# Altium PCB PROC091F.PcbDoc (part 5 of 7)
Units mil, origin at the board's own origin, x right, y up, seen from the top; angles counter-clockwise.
Board outline 3590.95 x 906.17 mil, 8 copper layers (Top Layer, GND1, Sig1, PWR1, PWR2, Sig2, GND2, Bottom Layer), stack 63.146 mil thick; 420 components, 316 nets, 1432 pads, 774 vias.
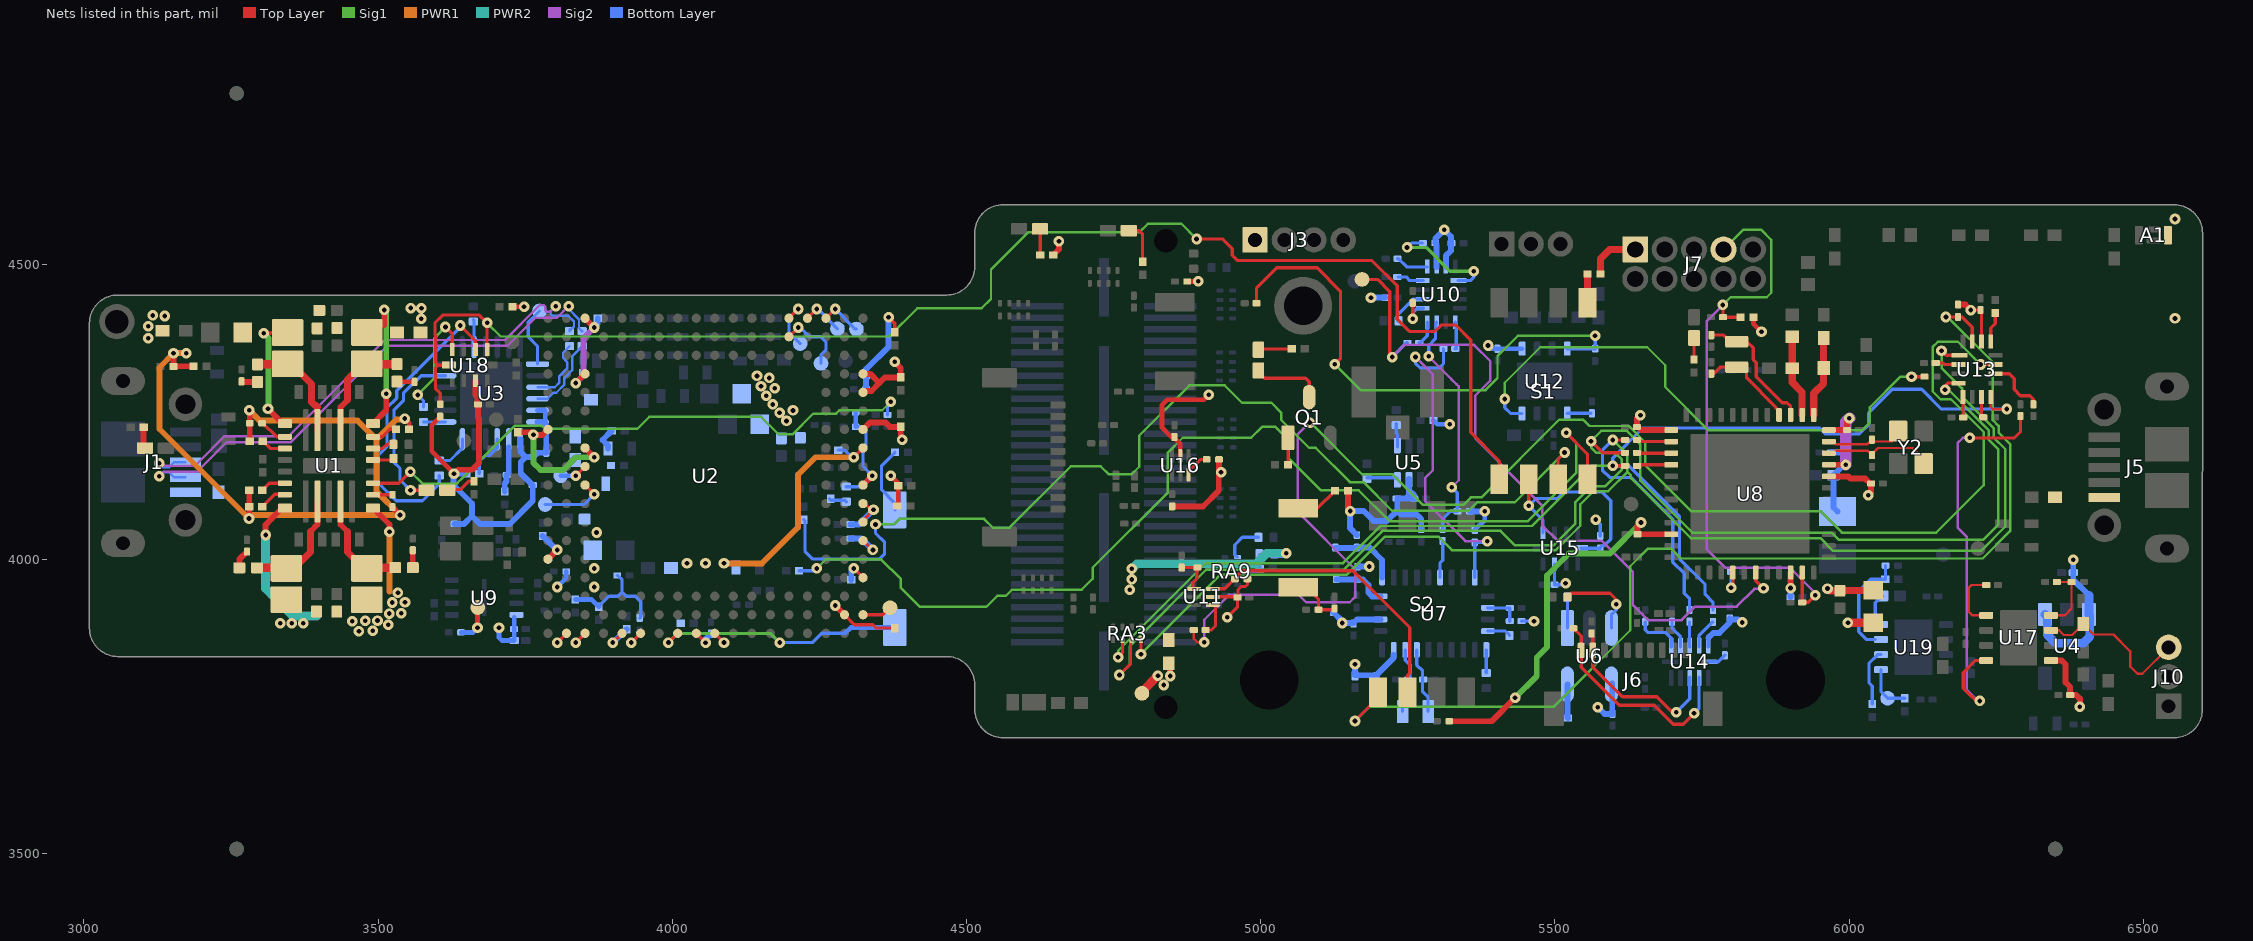
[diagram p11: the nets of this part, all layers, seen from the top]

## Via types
v1: diameter 18, hole 8, Top Layer to Bottom Layer, tented both sides, 737 vias
v2: diameter 19.68, hole 7.87, Top Layer to Bottom Layer, tented both sides, 36 vias
v3: diameter 17, hole 8, Top Layer to Bottom Layer, tented both sides, 1 vias

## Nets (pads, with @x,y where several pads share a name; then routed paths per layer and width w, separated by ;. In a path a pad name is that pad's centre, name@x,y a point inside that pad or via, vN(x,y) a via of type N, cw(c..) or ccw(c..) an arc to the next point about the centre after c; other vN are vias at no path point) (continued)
NetJ10_3: J10.3 R114.2 U17.7 | length 279.6
  Top Layer w4: U17.7@6343.09,3878.8 6356.9,3878.8 6364.64,3871.05 6379.2,3871.05 R114.2@6397.76,3889.61 6415.45,3871.92 6422.58,3871.92 6448.98,3871.92 6477.7,3843.2 6477.7,3817.28 6489.93,3805.05 6498.05,3805.05 J10.3@6543,3850
NetLD1_1: LD1.1 R39.2 | length 36.4
  Top Layer w10: R39.2@3101.69,4224 3101.69,4190.75 LD1.1@3103.94,4188.5
NetLD2_1: LD2.1 R13.2 | length 45.6
  Top Layer w5.5: R13.2@4625.39,4516.76 4625.39,4559.66 4626.81,4561.07 LD2.1@4627.29,4561.55
NetLD3_2: LD3.2 R42.1 | length 70.9
  Top Layer w5.5: LD3.2@4777.82,4558.15 4793.46,4558.15 4799.25,4552.36 R42.1@4799.25,4505.25
NetLD4_1: LD4.1 U3.17 | length 293.7
  Top Layer w5.5: v1(3555.07,4117.07) LD4.1@3582.28,4117.07
  Bottom Layer w5.5: v1(3555.07,4117.07) 3537.25,4134.89 3537.25,4154.13 3527,4164.38 3527,4252.77 3543.12,4268.88 3543.12,4281.51 3573.33,4311.72 U3.17@3614.31,4311.72
NetLD4_2: LD4.2 R15.2 | length 51.7
  Top Layer w5.5: LD4.2@3617.72,4117.07 3618.77,4118.12 3639.5,4118.12 3653.89,4132.51 R15.2@3663,4132.51
NetLD5_1: LD5.1 R107.2 | length 57.1
  Top Layer w5.5: LD5.1@4996.12,4355.74 4997.56,4357.18 R107.2@5052.59,4357.18
NetLD5_2: LD5.2 Q1.3 | length 121.4
  Top Layer w5.5: LD5.2@4996.12,4320.31 4996.12,4317.97 5006.72,4307.37 5076.23,4307.37 5082.37,4301.23 Q1.3@5082.37,4275.33
NetLD6_1: LD6.1 R17.2 | length 36.5
  Top Layer w5.5: R17.2@5736.37,4339.19 LD6.1@5736.37,4375.65
NetQ1_1: Q1.1 R108.2 | length 46.3
  Top Layer w5.5: R108.2@5046.35,4159.98 Q1.1@5046.35,4206.3
NetR2_2: R2.2 R174.1 | length 30.8
  Bottom Layer w5.5: R174.1@4267.1,4102.78 4269.74,4100.14 4271.74,4100.14 4293.06,4100.14 R2.2@4295.7,4097.5
NetR16_2: R16.2 S1.5 | length 49
  Top Layer w12: S1.5@5555.37,4435.46 R16.2@5555.37,4484.46
NetR20_2: R20.2 R29.2 U19.3 | length 178.8
  Bottom Layer w5.5: U19.3@6044.25,3863.26 6029.94,3863.26 6016.37,3876.83 6016.37,3945.46 6036.85,3965.94 R29.2@6061.35,3965.94 6061.6,3966.19 6061.6,3988.69 R20.2@6061.85,3988.94
NetR24_2: R24.2 U19.4 | length 62
  Bottom Layer w5.5: U19.4@6055.1,3888.6 6049.8,3888.6 6044.25,3894.15 6044.25,3926.09 6055.62,3937.46 R24.2@6056.47,3937.46
NetR27_2: R27.2 TP10.1 U19.1 | length 82.5
  Bottom Layer w5.5: U19.1@6054.25,3812.08 6054.25,3774.58 TP10.1@6065.37,3763.46 6094.48,3763.46 R27.2@6094.58,3763.57
NetR30_2: R30.2 U10.10 | length 65.1
  Bottom Layer w5.5: R30.2@5232.52,4404.87 5232.52,4415.19 5259.18,4441.85 U10.10@5276.29,4441.85
NetR40_2: R40.2 U3.9 | length 75.4
  Bottom Layer w5.5: R40.2@3671.81,4145.37 3671.81,4165.8 3681.85,4175.84 3689.03,4175.84 3702.45,4189.27 U3.9@3702.49,4203.87
NetR41_1: R41.1 U3.3 | length 115.3
  Bottom Layer w4: U3.3@3770.97,4292.04 3800.14,4292.04 3808.12,4300.03 3808.12,4311.17 3821.34,4324.39 3821.34,4334.97 3814.23,4342.08 3814.23,4350.59 3825.31,4361.66 R41.1@3825.31,4361.83
NetR51_2: R51.2 U5.1 | length 40.2
  Bottom Layer w5.5: R51.2@5230.37,4230.36 5230.37,4214.38 5232.29,4212.46 U5.1@5232.29,4190.93
NetR57_2: R57.2 U5.6 | length 52.4
  Bottom Layer w5.5: R57.2@5180.56,4138.17 5230.73,4138.17 U5.6@5232.29,4136.6
NetR58_2: R58.2 RA9.5 | length 68.7
  Bottom Layer w5.5: RA9.5@4960.68,4003.38 4959.62,4003.38 4956,4007 4956,4024 4968.94,4036.94 R58.2@4996.2,4036.94
NetR60_1: R60.1 U3.4 | length 133.5
  Bottom Layer w4: U3.4@3770.97,4272.35 3788.06,4272.35 3798.3,4282.59 3802.71,4282.59 3816.62,4296.51 3816.62,4307.65 3829.84,4320.87 3829.84,4344.29 3846.82,4361.26 R60.1@3846.82,4361.83
NetR61_2: R61.2 U3.13 | length 37.1
  Bottom Layer w5.5: R61.2@3577.24,4232.98 U3.13@3614.31,4232.98
NetR62_1: R62.1 U3.20 | length 47.1
  Bottom Layer w5.5: R62.1@3662,4407.2 3663.08,4406.12 U3.20@3663.12,4360.53
NetR63_1: R63.1 U3.12 | length 63.3
  Bottom Layer w5.5: R63.1@3604,4167.58 3622.29,4167.58 3643.43,4188.72 U3.12@3643.43,4203.87
NetR66_2: R66.2 R122.1 U12.8 | length 917.7
  Top Layer w5.5: R66.2@4992.9,4434.77 4992.9,4460.9 5027,4495 5096,4495 5135.53,4455.47 5135.53,4340.53 v1(5126,4331)
  Sig1 w4.2: v1(5126,4331) 5169.73,4287.27 5382.12,4287.27 5402.37,4307.51 5402.37,4345 5436.98,4379.61 v1(5568.26,4379.61)
  Bottom Layer w5.5: U12.8@5520.96,4357.63 R122.1@5568.37,4357.63 5568.37,4379.49 v1(5568.26,4379.61)
NetR67_2: R67.2 U6.1 | length 52.6
  Bottom Layer w5.5: U6.1@5521.17,3882.9 R67.2@5521.17,3935.46
NetR68_2: R68.2 U6.3 | length 142.4
  Top Layer w5.5: R68.2@5521.17,3935.46 5527.83,3942.12 5593.59,3942.12 5604.37,3931.35 v1(5604.37,3923.46)
  Bottom Layer w5.5: U6.3@5595.94,3882.87 5595.94,3905.07 5604.37,3913.5 v1(5604.37,3923.46)
NetR69_2: R69.2 U6.5 | length 57.6
  Bottom Layer w10: U6.5@5521.13,3787.16 5521.13,3730.92 R69.2@5522.09,3729.96
NetR70_1: R70.1 U7.19 | length 40.4
  Bottom Layer w5.5: U7.19@5385.92,3877.69 5416,3877.69 5422.58,3871.12 R70.1@5422.58,3870.14
NetR71_1: R71.1 U7.20 | length 39.5
  Bottom Layer w5.5: R71.1@5383.33,3806.26 5383.33,3845.57 U7.20@5383.46,3845.7
NetR72_2: R72.2 R73.2 U7.17 | length 60
  Bottom Layer w5.5: U7.17@5385.92,3917.06 R73.2@5423.36,3917.06 R72.2@5423.37,3894.46
NetR74_2: R74.2 U11.4 | length 56.4
  Top Layer w5.5: R74.2@4906.37,3879.46 4916.22,3879.46 4923.22,3886.46 4923.22,3919.14 U11.4@4920.42,3921.94
NetR76_1: R76.1 U14.8 | length 47.5
  Bottom Layer w5.5: R76.1@5698.97,3892.42 5698.97,3882.19 5713.48,3867.67 U14.8@5713.48,3850.95
NetR79_1: R79.1 U14.12 | length 32.5
  Bottom Layer w5.5: U14.12@5760.73,3825.36 5777.58,3825.36 R79.1@5788.67,3836.45
NetR86_2: R86.2 U8.15 | length 58.7
  Top Layer w5.5: R86.2@5639.23,4180.57 5639.8,4180.01 U8.15@5697.71,4180.01
NetR87_2: R87.2 U8.14 | length 59.5
  Top Layer w5.5: R87.2@5639.38,4202.46 5642.16,4199.69 U8.14@5697.71,4199.69
NetR92_1: R92.1 U19.2 | length 98.3
  Bottom Layer w5.5: R92.1@6039.37,3753.68 6039.37,3784.11 6033.69,3789.79 6033.69,3822.99 6048.37,3837.67 U19.2@6054.25,3837.67
NetR97_1: R97.1 U7.11 | length 63
  Bottom Layer w5.5: U7.11@5304.72,3968.74 5304.72,3993.45 5309.27,3998 R97.1@5309.27,4029.9
NetR99_1: R99.1 U10.12 | length 45.7
  Bottom Layer w5.5: R99.1@5233.13,4479.52 5247.22,4479.52 5253.4,4473.35 U10.12@5276.29,4473.35
NetR100_2: R100.2 U10.5 | length 48
  Bottom Layer w5.5: U10.5@5330.42,4402.48 5332.42,4400.48 5332.42,4357.63 5330.42,4357.63 R100.2@5330.67,4357.38
NetR101_1: R101.1 U10.13 | length 56.6
  Bottom Layer w5.5: R101.1@5232.37,4510.46 5234.17,4510.46 5248.14,4496.49 U10.13@5283.18,4496.49
NetR105_1: R105.1 R106.1 U11.1 | length 64.2
  Top Layer w5.5: R105.1@4865.78,3985.56 4891.33,3985.56 4891.33,3966.85 4884.99,3960.5 U11.1@4884.99,3949.5
NetR111_1: R111.1 SW3.2 | length 87.5
  Top Layer w5.5: SW3.2@5051.37,4086.32 5096.23,4086.32 R111.1@5126.37,4116.46
NetR112_2: R112.2 U10.8 | length 41.8
  Bottom Layer w5.5: R112.2@5269.37,4367.46 5271.17,4367.46 5283.18,4379.47 U10.8@5283.18,4402.48
NetR113_2: R113.2 U10.9 | length 58
  Top Layer w5.5: v1(5258.37,4408.46) R113.2@5258.37,4435.46
  Bottom Layer w5.5: v1(5258.37,4408.46) 5258.37,4418.25 5266.22,4426.11 U10.9@5275.3,4426.11 U10.9@5276.29,4426.11
NetR115_2: R115.2 R134.1 U17.8 | length 109.7
  Top Layer w4: U17.8@6343.09,3904.39 6366.36,3904.39 6377.97,3916 R134.1@6377.97,3961 R115.2@6352.99,3961
NetR116_1: R116.1 U17.1 | length 104.7
  Top Layer w4: U17.1@6232.85,3904.39 6209.58,3904.39 6202.97,3911 6202.97,3951 6207.97,3956 R116.1@6232.97,3956
NetR120_1: R120.1 U17.4 | length 709.3
  Top Layer w5.5: v1(6205,4206) 6281,4206 6291,4216 R120.1@6291,4242.98 ; v1@6223,3758 v1(6222,3759) 6216,3759 6208.01,3766.99 6207.53,3766.99 6194,3780.52 6194,3807.03 6214.58,3827.61 U17.4@6232.85,3827.61
  Sig2 w4.2: v1(6205,4206) 6193,4206 6184.36,4197.36 6184.36,4053.64 6199.58,4038.42 6199.58,3778.41 6218.99,3759 v1(6222,3759)
NetR121_1: R121.1 U13.2 | length 39.5
  Top Layer w5.5: R121.1@6147.25,4333.23 6159.77,4333.23 6162.37,4330.63 U13.2@6185.63,4330.63
NetR123_1: R123.1 U12.1 | length 40.6
  Bottom Layer w5.5: U12.1@5520.96,4247.39 5521.31,4247.74 R123.1@5561.37,4247.74
NetR125_2: R125.2 R129.1 SW3.1 | length 103.2
  Top Layer w5.5: SW3.1@5051.37,3952.46 5077.69,3952.46 5098.17,3931.98 R125.2@5098.17,3914.04 5123.33,3914.04 R129.1@5125.2,3915.92 ; R129.1@5123.7,3917.42 R129.1@5125.2,3918.92
NetR127_1: R127.1 U12.4 | length 947.1
  Top Layer w5.5: v1(6106,4310) R127.1@6127.98,4310
  Sig1 w4.2: v1(5414.67,4272) 5414.67,4299.67 5475,4360 5656.88,4360 5687.4,4329.48 5687.4,4292.6 5761.21,4218.79 6021.79,4218.79 6035.3,4232.3 6035.3,4258 6087.3,4310 v1(6106,4310)
  Bottom Layer w5.5: v1(5414.67,4272) 5414.67,4257.46 5424.74,4247.39 U12.4@5444.19,4247.39
NetR128_1: R128.1 U13.5 | length 35
  Top Layer w5.5: U13.5@6193.5,4275.51 6193.5,4241.13 R128.1@6193.93,4240.71
NetR131_2: R131.2 U8.29 | length 53.8
  Top Layer w5.5: v1(5799.35,3951.46) 5802.04,3954.16 U8.29@5802.04,3977.25
  Bottom Layer w5.5: v1(5799.35,3951.46) R131.2@5799.35,3978.41
NetR136_1: R136.1 U13.7 | length 35.8
  Top Layer w5.5: U13.7@6225,4275.51 6225,4244 R136.1@6228,4241
NetR139_1: R139.1 U13.10 | length 104.2
  Top Layer w5.5: U13.10@6248.62,4314.88 6272,4314.88 6280.5,4306.38 6280.5,4288.27 6291.05,4277.72 6307.28,4277.72 6313,4272 R139.1@6313,4263 R139.1@6311.28,4264.72
NetR141_1: R141.1 U13.13 | length 51.3
  Top Layer w5.5: U13.13@6240.75,4370 6240.75,4392.75 6248.22,4400.22 R141.1@6248.22,4418.23
NetR160_1: R160.1 U14.10 | length 52.7
  Bottom Layer w5.5: U14.10@5744.98,3850.95 5744.98,3870.7 5745.08,3870.7 5766.49,3892.11 5766.49,3892.21 5767.54,3893.26 R160.1@5768.53,3893.26
NetR161_2: R161.2 U8.16 | length 59.1
  Top Layer w5.5: R161.2@5639.38,4158.46 5641.24,4160.32 U8.16@5697.71,4160.32
NetR166_1: R166.1 U14.9 | length 41.8
  Bottom Layer w5.5: R166.1@5728.8,3892.57 5728.8,3851.38 U14.9@5729.23,3850.95
NetR168_1: R168.1 U14.7 | length 77.4
  Bottom Layer w5.5: R168.1@5653.43,3892.54 5653.43,3879.64 5657.71,3875.36 5687.51,3875.36 5697.73,3865.14 U14.7@5697.73,3850.95
NetR176_1: R176.1 S3.1 | length 117
  Bottom Layer w5.5: S3.1@4378.33,4083.66 4378.33,4095.26 4355.69,4117.91 4355.69,4158.92 R176.1@4378.58,4181.8
NetR178_2: R178.2 U16.3 | length 44.7
  Top Layer w5.5: U16.3@4877.15,4143.71 4877.15,4148.84 4897.78,4169.46 R178.2@4908.17,4169.46
NetTP2_1: TP2.1 U2.C10 | length 47.8
  Top Layer w5.5: v1(3836.01,4141.61) U2.C10@3851.76,4157.36
  Bottom Layer w8: TP2.1@3810.59,4141.77 3835.85,4141.77 v1(3836.01,4141.61)
NetTP3_1: TP3.1 U2.C9 | length 113
  Top Layer w5.5: U2.C9@3851.76,4125.86 v1(3867.5,4110.11)
  Bottom Layer w5.5: TP3.1@3784,4092.76 3850.15,4092.76 v1(3867.5,4110.11)
NetTP6_1: TP6.1 U2.T18 | length 72.5
  Top Layer w5.5: U2.T18@4261.2,4409.33 v1(4276.95,4425.07)
  Bottom Layer w5.5: v1(4276.95,4425.07) 4311.08,4390.94 TP6.1@4313,4390.94
NetTP7_1: TP7.1 U2.R18 | length 71.4
  Top Layer w5.5: U2.R18@4229.71,4409.33 v1(4245.46,4425.07)
  Bottom Layer w5.5: v1(4245.46,4425.07) 4247.21,4425.07 TP7.1@4280.69,4391.59
NetTP8_1: TP8.1 U2.P17 | length 119.4
  Top Layer w5.5: U2.P17@4198.21,4377.83 v1(4213.96,4393.58)
  Bottom Layer w5.5: v1(4213.96,4393.58) 4217.13,4393.58 4232.89,4377.82 4251.98,4377.82 4261.2,4368.6 4261.2,4355.7 4252.7,4347.19 TP8.1@4252.7,4332.6
NetTP9_1: TP9.1 U2.P18 | length 95.6
  Top Layer w5.5: U2.P18@4198.21,4409.33 v1(4213.96,4425.07)
  Bottom Layer w5.5: v1(4213.96,4425.07) 4198.22,4409.33 4198.22,4385.27 TP9.1@4217.3,4366.19
NetTP11_1: TP11.1 U2.V2 | length 50.8
  Top Layer w5.5: U2.V2@4324.2,3905.39 4358.02,3905.39 TP11.1@4370,3917.37
NetTP26_1: TP26.1 U3.1 | length 104.7
  Bottom Layer w5.5: U3.1@3770.97,4331.41 3770.97,4362.04 3755.27,4377.75 3755.27,4402.47 TP26.1@3774.42,4421.63
nRESET: C37.1 J7.7 R89.1 R91.1 U8.35 | length 1057.2
  Top Layer w5.5: v1(5785.39,4431.94) C37.1@5785.39,4411.08 R89.1@5815.36,4411.08 ; U8.35@5920.15,3977.25 R91.1@5920.15,3926.46 5930.43,3926.46 v1(5942.41,3938.44)
  Sig1 w4.2: v1(5785.39,4431.94) 5798.5,4445.04 5859.97,4445.04 5867.61,4452.68 5867.61,4542.36 5849.97,4560 5820.28,4560 J7.7@5786.47,4526.19
  Sig2 w4.2: v1(5785.39,4431.94) 5758.35,4404.89 5758.35,4016.29 5789.04,3985.6 5899.11,3985.6 5942.41,3942.3 v1(5942.41,3938.44)
PGOOD: R31.1 R37.2 RA9.7 | length 66.9
  Bottom Layer w5.5: RA9.7@4960.68,3971.89 4961.37,3972.58 4970.57,3972.58 4974.12,3976.14 4978.8,3976.14 4982,3979.33 4994.2,3979.33 R37.2@4998.2,3983.33 R31.1@4998.2,4008
PMIC_1V0: C46.1 C49.1 C54.1 L4.1 L12.1 L14.1 U1.1 | length 153.6
  Top Layer w10: U1.1@3491.41,4086.67 3519.37,4058.71 v1(3519.37,4046.65)
  PWR1 w10: 3519.37,3944.69 v1(3519.37,4046.65)
  other v1: 3467.48,3877.51 3491.19,3878.19 3517.25,3888.26 3456.15,3894.32 3478.45,3895.02 3499.06,3895.51 3518.86,3907.41 3539.19,3908.06 3524.08,3926.16 3545.78,3926.72 3533.81,3942.78 4194.19,4234.78 4182.39,4248.85 4205.2,4252.61 4170.91,4262.86 4159.95,4277.76 4174.38,4290.49 4150.85,4293.59 4164.94,4307.84 4143.91,4311.32
PMIC_1V2: C45.1 C77.1 L3.1 L13.1 U1.14 | length 216.3
  Top Layer w5.5: v1@3313.92,4383.94 3316.96,4383.94 3318.07,4385.05 L3.1@3346.24,4385.05 L3.1@3358.24,4385.05 ; U1.14@3337.87,4230.37 U1.14@3341.81,4230.37
  Top Layer w10: v1(3312.99,4255.25) U1.14@3337.87,4230.37
  Sig1 w10: v1(3305.92,4383.94) 3313.92,4375.94 3313.92,4256.18 v1(3312.99,4255.25)
PMIC_1V2_FILTERED: C91.1 C92.1 C94.1 C95.1 C96.1 C97.1 C98.1 C103.1 FL6.2 U2.A5 U2.C1 U2.E1 U2.J1 U2.V4 U2.V6 U2.V7 U2.V8 U2.V12 U2.V14 U2.V15 | length 622
  Top Layer w5.5: v1(3836.01,3858.15) U2.C1@3851.76,3873.89 ; v1(3899,3858.15) U2.E1@3914.75,3873.89 ; U2.J1@4040.84,3873.78 v1(4056.59,3858.04) ; v1(4308.45,3984.13) U2.V4@4324.2,3968.38 ; U2.V6@4324.2,4031.37 v1@4339.94,4015.63 ; U2.V7@4324.2,4062.87 4324.2,4065.87 v1(4341.94,4083.62) 4339.55,4086.01 4335.33,4086.01 4326.97,4094.37 U2.V8@4324.2,4094.37
  Top Layer w10: U2.A5@3788.76,3999.88 v1(3804.51,4015.63) ; U2.V12@4324.2,4220.35 4335.73,4231.88 4362.85,4231.88 4370,4224.73 C96.1@4388.37,4224.73 4388.37,4205.15 v1(4390.55,4202.96) ; U2.V14@4324.2,4283.34 4324.2,4285.59 4338.42,4285.59 4352,4299.17 ; U2.V15@4324.2,4314.84 4336.34,4314.84 4352,4299.17 ; v1(4378,4335.17) 4388.37,4324.81 C98.1@4388.37,4308.78 4361.61,4308.78 4352,4299.17
  Bottom Layer w10: C97.1@3779.79,4039.17 3803.34,4015.63 v1(3804.51,4015.63) ; v1(3899,3858.15) 3899.78,3858.15 C95.1@3922.37,3880.73 ; v1(4056.59,3858.04) 4056.59,3863.94 C92.1@4065.74,3873.08 ; C91.1@4303,4035.17 4321.4,4035.17 v1(4340.94,4015.63) ; C103.1@4303,4058.8 4317.13,4058.8 v1(4341.94,4083.62) ; C94.1@4304.21,3964.68 4304.21,3979.89 v1(4308.45,3984.13)
  other v1: 3109.58,4375.35 3109.39,4395.84 3137.27,4413.1 3117.35,4414.06
PMIC_1V8: C47.1 C48.1 L5.1 L11.1 U1.21 | length 258.9
  Top Layer w10: v1(3309,4041) 3309,4058.32 3319,4068.32 3337.35,4086.67 U1.21@3341.81,4086.67
  PWR2 w15: v1(3309,4041) 3309,3950.08 3319,3940.08 3356.06,3903.02 3395.6,3903.02
  other v1: 3333.85,3890.74 3353.35,3890.74 3372.84,3890.74 3867.5,3952.63 3867.5,3984.13 3871.34,4045.2
PMIC_3V3: C44.1 FL20.2 L2.1 U1.8 | length 229.5
  Top Layer w10: U1.8@3491.41,4230.37 3513.87,4252.83 v1(3513.87,4281) ; 3510.62,4397.75 v1(3510.62,4423.47)
  Sig1 w10: v1(3510.62,4423.47) 3513.87,4420.22 v1(3513.87,4281)
PMIC_CLK: R103.2 U1.3 | length 1007.7
  Top Layer w5.5: U1.3@3491.41,4128.99 3535.47,4128.99 v1(3555,4148.52)
  Sig1 w4.2: v1(3555,4148.52) 3575.22,4128.3 3633.73,4128.3 3635.41,4129.97 ; 3635.45,4129.97 3644.41,4138.94 ; 3644.41,4138.98 3731.89,4226.46 3778.57,4226.46 3783.54,4221.5 3940.72,4221.5 3960.9,4241.68 4151.25,4241.68 4180.97,4211.97 4204.31,4211.97 4239.64,4247.29 4278.29,4247.29 4283.99,4252.99 4356.92,4252.99 v1(4371.44,4267.52)
  Bottom Layer w5.5: R103.2@4365.65,4245.1 4365.65,4261.72 v1(4371.44,4267.52)
PMIC_EN1: R34.1 U1.7 | length 44.4
  Top Layer w5.5: U1.7@3491.41,4207.73 3507.24,4207.73 3520.15,4220.64 R34.1@3530.48,4220.64
PMIC_EN2: R35.1 U1.15 | length 48.4
  Top Layer w5.5: R35.1@3303.04,4231 3304.38,4231 3327.64,4207.73 U1.15@3341.81,4207.73
PMIC_EN3: R36.1 U1.2 | length 33.2
  Top Layer w5.5: U1.2@3491.41,4109.31 R36.1@3524.56,4109.31
PMIC_NINT: R26.1 U1.19 | length 43.6
  Top Layer w5.5: R26.1@3303.16,4116.99 3315.16,4128.99 U1.19@3341.81,4128.99
PMIC_NRST: R33.1 U1.20 | length 47.8
  Top Layer w5.5: R33.1@3303.16,4088.65 3324.5,4110 3341.11,4110 U1.20@3341.81,4109.31
PMIC_PGOOD: R25.1 U1.16 | length 43
  Top Layer w5.5: R25.1@3304,4200.49 3316.45,4188.05 U1.16@3341.81,4188.05
PMIC_SCL: R32.2 U1.5 | length 36
  Top Layer w5.5: U1.5@3491.41,4168.36 3523.7,4168.36 R32.2@3526.34,4171
PMIC_SDA: R28.2 U1.6 | length 37.7
  Top Layer w5.5: U1.6@3491.41,4188.05 3508.15,4188.05 3515.6,4195.5 R28.2@3526,4195.5
PMICOUT_3V3: C2.2 C3.2 C87.1 C88.1 C100.1 C101.1 C102.1 C126.1 FL20.1 FL22.1 R2.1 R4.1 R5.1 R7.2 R8.2 R9.1 R19.2 R21.2 R22.2 R23.2 R31.2 R40.1 R43.2 R44.2 R45.2 R59.2 R75.1 S3.2 TP5.1 U2.H1 U2.V9 U3.5 U3.6 U3.7 U9.8 U18.8 | length 2389.6
  Top Layer w5.5: v1(3993.49,3858.15) U2.H1@4009.24,3873.89
  Top Layer w6: v1(4367.63,4410.91) 4378.13,4400.41 R5.1@4378.13,4385.29
  Top Layer w8: R19.2@3605.65,4241.65 3591.37,4227.36 3591.37,4183.02 v1(3629.11,4145.27) ; v1(3669.07,3883.19) 3669.07,3917.49 TP5.1@3669.3,3917.72 ; R4.1@3728.57,4429.01 3748.07,4429.01 v1(3748.13,4428.95) ; v1(4371.44,4141.61) 4383.88,4129.17 C88.1@4383.88,4124.76 4383.88,4094.76 C102.1@4379.37,4090.24
  Top Layer w10: v1(3629.11,4145.27) 3635.73,4151.89 3659.99,4151.89 3671.7,4163.61 3671.7,4239.21 3669.91,4241 C126.1@3669.91,4262.91 3668.9,4261.9 3668.9,4275.32 3665.64,4278.59 U18.8@3665.64,4303.01 ; U2.V9@4324.2,4125.86 v1(4339.94,4141.61)
  Sig1 w5.5: v1(3993.49,3858.15) 4008.74,3873.4 4167.21,3873.4 v1(4182.46,3858.15)
  PWR2 w15: v1(4780.64,3983.52) 4781.14,3983.52 4789.76,3992.13 4992.13,3992.13 5009.96,4009.96 v1(5043.37,4009.96)
  Bottom Layer w5.5: R75.1@3875.37,3918.83 3875.37,3919.78 3892.48,3936.89 3907.55,3936.89 3914.61,3943.95 ; R8.2@3906.38,3972.12 3907.67,3972.12 3914.74,3965.05 3914.74,3944.08 3914.61,3943.95 ; R7.2@3944.52,3899.73 3946.24,3901.44 3946.24,3927.66 3937.02,3936.88 3921.68,3936.88 3914.61,3943.95 ; v1(4182.46,3858.15) 4238.15,3858.15 4253.89,3873.89 4293.39,3873.89 ; R2.1@4295.7,4123.1 4321.43,4123.1 v1(4339.94,4141.61) 4324.2,4157.36 4324.2,4186.5 4329,4191.3 4329,4220.2 4324.44,4224.76 R59.2@4311.76,4224.76
  Bottom Layer w8: R43.2@3641.22,3875.43 3661.3,3875.43 v1(3669.07,3883.19) ; v1(3705.55,3883.32) 3705.55,3866.38 3710.23,3861.69 C100.1@3731.37,3861.69 U9.8@3731.37,3901.12 ; U3.5@3770.97,4252.67 3783.91,4252.67 U3.6@3783.91,4232.98 ; v1(3804.51,3952.63) 3819.73,3967.86 R45.2@3819.73,3978.91 ; R9.1@3835,3931.22 3862.97,3931.22 R75.1@3875.37,3918.83 ; 4293.39,3873.89 4303.2,3883.7 S3.2@4378.13,3883.7 ; R59.2@4311.76,4224.76 R23.2@4311.76,4249.29 ; v1(4777.34,3947.7) v1@4777.56,3947.48
  Bottom Layer w10: R44.2@3629.89,4059.85 3646.26,4059.85 3659.8,4073.39 ; R40.1@3649.76,4145.37 3628.21,4145.37 3628.11,4145.27 3628.11,4126.02 3659.8,4094.33 3659.8,4073.39 ; U3.7@3741.86,4203.87 3741.86,4182.84 3751.18,4173.52 ; U3.6@3770.97,4232.98 3783.91,4232.98 3783.91,4229.09 3785.88,4227.12 C2.2@3785.88,4180.75 3771.42,4180.75 3764.16,4173.52 3751.18,4173.52 ; R22.2@4329.48,4288.76 R21.2@4329.48,4310.76 4329.48,4322.94 4367.63,4361.09 v1(4367.63,4410.91) ; 3659.8,4073.39 3673.75,4059.44 3723.24,4059.44 3762.94,4099.14 C3.2@3762.94,4125.72 3742.56,4146.1 3742.56,4164.9 3751.18,4173.52
  Bottom Layer w15: R31.2@5023.3,4008.93 5023.67,4009.31 5041.9,4009.31 5042.56,4009.96 v1(5043.37,4009.96)
  other v1: 4780.6,3965.46 3573.52,4408.24 3573.7,4426.43 3555.52,4426.61
PMICVIO_3V3: R25.2 R26.2 R33.2 R34.2 R35.2 R36.2 R50.1 R52.2 | length 1279.6
  Top Layer w8: v1(3545.33,4238.82) 3553.02,4231.13 R34.2@3553.02,4218.5
  Top Layer w10: v1(3152.43,4349.59) R52.2@3152.43,4327.36 3152.8,4327.73 R50.1@3186.38,4327.73 ; v1(3280.71,4069) 3281.11,4069.4 R33.2@3281.11,4088.65 R26.2@3281.11,4116.99 ; v1(3281.33,4253) 3282,4253 R35.2@3282,4231 R35.2@3282,4231 R25.2@3281.95,4200.49 ; R36.2@3524.26,4087.97 v1(3537.4,4074.84)
  PWR1 w10: v1(3174.29,4349.96) 3152.8,4349.96 v1(3152.43,4349.59) 3128.56,4325.73 3128.56,4221.15 v1(3280.71,4069) 3286.55,4074.84 v1(3537.4,4074.84) 3497.61,4114.63 3497.61,4202.73 ; v1(3281.33,4253) 3299.07,4235.25 3465.09,4235.25 3497.61,4202.73 ; v1@3546.33,4237.27 3530.99,4237.27 3497.61,4203.89 3497.61,4202.73
PS0: R77.2 R93.1 U7.6 | length 117.9
  Bottom Layer w10: R93.1@5126.93,4019.06 R77.2@5163.41,4019.06 ; R77.2@5163.43,4019.54 5185.29,4019.54 5206.22,3998.62 5206.22,3968.81 U7.6@5206.3,3968.74
PS1: R78.2 R98.1 U7.5 | length 94.8
  Bottom Layer w10: R98.1@5128.47,3965.22 5128.56,3965.32 5164.52,3965.32 5173.79,3965.32 5183.14,3955.97 5183.14,3943.02 5189.41,3936.75 U7.5@5203.84,3936.75
RE: A1.1
  other v1: 6553.69,4409 6553.69,4578
RESETN: R94.1 U10.1 | length 198.6
  Sig1 w5.5: v1(5248.71,4529.61) 5281.03,4529.61 5321.61,4489.04 v1(5362.03,4489.04)
  Bottom Layer w5.5: v1(5248.71,4529.61) 5256.18,4537.08 R94.1@5275.16,4537.08 ; U10.1@5335.34,4473.35 5356.12,4473.35 5362.03,4479.26 v1(5362.03,4489.04)
RF_N: C23.1 L6.1 U8.2 | length 139.8
  Top Layer w12: L6.1@5903.37,4377.75 5903.28,4377.66 C23.1@5903.28,4324.42 5903.28,4300.45 5920.15,4283.58 U8.2@5920.15,4244.97
RF_P: C22.2 L1.1 U8.1 | length 137.8
  Top Layer w12: U8.1@5939.84,4244.97 5939.84,4281.73 5956.71,4298.6 L1.1@5956.71,4324.41 C22.2@5956.7,4375.79
SENS_INT: R18.2 R100.1 U7.14 | length 567.6
  Sig2 w4.2: v1(5262.94,4343.4) 5292.48,4313.87 5292.48,4151.03 5279.43,4137.99 5279.43,4098.76 5347.73,4030.46 v1(5384.96,4030.46)
  Bottom Layer w5.5: v1(5262.94,4343.4) 5262.94,4333.01 5271.25,4324.69 5303.04,4324.69 5310.65,4332.3 R100.1@5310.65,4357.38 ; U7.14@5363.78,3968.74 R18.2@5363.78,4028.46 5381.91,4028.46 5383.91,4030.46 v1(5384.96,4030.46)
SENS_NRST: R81.2 R97.2 U10.7 | length 404.5
  Sig2 w4.2: v1(5285.37,4344.73) 5323.7,4306.4 5323.7,4306.04 5332.66,4297.07 5333.03,4297.07 5336.56,4293.54 5336.56,4134.06 v1(5324.41,4121.9)
  Bottom Layer w5.5: v1(5285.37,4344.73) 5285.37,4362.56 5296.92,4374.11 5296.92,4387.55 5297.74,4388.36 5297.74,4401.3 U10.7@5298.93,4402.48 ; R97.2@5309.27,4050.94 5309.27,4068.09 5322.37,4081.19 5333.89,4081.19 5333.89,4112.42 v1(5324.41,4121.9)
SOP0: R159.2 S1.3 | length 1765.9
  Top Layer w5.5: S1.3@5505.37,4135.46 5505.37,4170.08 v1(5516.37,4181.08)
  Sig1 w4.2: v1(4345.4,4058.9) 4376.9,4058.9 4386.3,4068.3 4529.8,4068.3 4544.6,4053.5 4573.3,4053.5 4677.5,4157.7 4728,4157.7 4741.9,4143.8 4780.4,4143.8 4793.6,4157 4793.6,4209.9 4878.9,4295.2 4938.86,4295.2 4968.4,4265.66 5018.16,4265.66 5034.8,4249.02 5034.8,4236.8 5082.3,4189.3 5093.2,4189.3 5151.65,4130.85 5174.55,4130.85 5223.5,4081.9 5352.7,4081.9 5367.29,4096.49 5431.78,4096.49 v1(5516.37,4181.08)
  Bottom Layer w5.5: R159.2@4223.5,4067.08 4225.4,4065.18 4225.4,4013.55 4238.97,3999.98 4351.98,3999.98 4360.8,4008.8 4360.8,4028.8 4345.4,4044.2 v1(4345.4,4058.9)
SOP1: R171.2 S1.4 | length 1835.5
  Top Layer w5.5: v1(5519.37,4214.46) 5555.37,4178.46 S1.4@5555.37,4135.46
  Sig1 w4.2: v1(4245.46,3984.13) 4260.76,3999.43 4355.03,3999.43 4388.5,3965.96 4388.5,3950.96 4420.67,3918.79 4533.64,3918.79 4552.58,3937.72 4567.09,3937.72 4577.22,3947.85 4695.47,3947.85 4714.6,3966.98 4714.6,3985.6 4842.2,4113.2 4842.2,4180.88 4867.55,4206.23 4983.79,4206.23 5002.26,4224.7 5025,4224.7 5047,4202.7 5047,4172 5102.36,4116.64 5166.64,4116.64 5218.64,4064.64 5454.22,4064.64 5536.6,4147.02 5536.6,4197.23 v1(5519.37,4214.46)
  Bottom Layer w5.5: R171.2@4215.47,3980.18 4241.5,3980.18 v1(4245.46,3984.13)
SPI/CAN_MUX_CTRL: R118.1 S2.1 U13.15 | length 1875.8
  Top Layer w5.5: v1(5160.25,3724.93) 5199.37,3764.05 S2.1@5199.37,3773.46 ; v1(6164.48,4411.48) R118.1@6185,4411.48 6191.52,4411.48 6209.25,4393.75 U13.15@6209.25,4370
  Sig1 w4.2: v1(5160.25,3724.93) 5184.05,3748.73 5497.64,3748.73 5628,3879.09 5628,3987.76 5658,4017.76 5697.24,4017.76 5714,4001 6227,4001 6273.6,4047.6 6273.6,4195.4 6253.9,4215.1 6253.9,4226.25 6244,4236.15 6244,4334.64 6167.16,4411.48 v1(6164.48,4411.48)
SPI_CLK1: R160.2 R161.1 RA3.2 U13.8 | length 2179.9
  Top Layer w4.2: U13.8@6240.75,4275.51 6240.75,4258.25 6244,4255 v1(6268,4255)
  Top Layer w5.5: v1(4757.56,3832.95) 4765.06,3840.45 RA3.2@4765.06,3863.01 ; v1(5598.37,4158.46) R161.1@5619.36,4158.46
  Sig1 w4.2: v1(4757.56,3832.95) 4757.56,3844.16 4906.55,3993.15 5140.15,3993.15 5203.24,4056.24 5460.94,4056.24 5563.16,4158.46 v1(5598.37,4158.46)
  Bottom Layer w5.5: R160.2@5768.53,3913.29 5768.53,3926.85 5755.12,3940.26 5755.12,3956.82 5711.87,4000.07 5711.87,4072.39 5625.79,4158.46 v1(5598.37,4158.46) 5598.37,4171.72 5649.65,4223 5949,4223 5959.38,4212.62 6017.62,4212.62 6033,4228 6033,4248.48 6073.27,4288.75 6123.15,4288.75 6156.9,4255 v1(6268,4255)
SPI_CLK1_T: J6.1 R185.1 U14.2 | length 376.8
  Top Layer w5.5: R185.1@5531.37,3882.46 5544.58,3869.25 J6.1@5544.58,3845.06 5544.58,3815.96 5608.98,3751.57 5668.75,3751.57 5700.85,3719.47 5717.97,3719.47 v1(5736.47,3737.96)
  Bottom Layer w5.5: v1(5736.47,3737.96) 5744.98,3746.48 U14.2@5744.98,3799.77
SPI_CS1: R74.1 U13.11 | length 2511.8
  Top Layer w4.2: R74.1@4886.35,3879.46 4886.35,3864.65 4892.11,3858.89 v1(4904,3858.89)
  Top Layer w5.5: v1@6224.37,4330.63 U13.11@6248.62,4330.63
  Sig1 w4.2: v1(5083,4232) 5084.53,4232 5172.53,4144 5224,4144 5275.8,4092.2 5344.6,4092.2 5357.29,4104.89 5375.16,4104.89 5507.27,4237 5548,4237 5558.84,4226.16 5625.72,4226.16 5653.37,4198.51 5653.37,4159.76 5731.52,4081.6 5951,4081.6 5987.6,4045 6148,4045 6228.7,4125.7 6228.7,4215.82 6172.82,4271.7 6155.3,4271.7 6141.7,4285.3 6141.7,4360.34 6150.66,4369.3 6184.7,4369.3 v1(6223.37,4330.63)
  Sig2 w4.2: v1@4900.71,3862.18 v1(4904,3858.89) 4904,3897 4946.3,3939.3 5064.58,3939.3 5077.18,3926.7 5151.31,3926.7 5160.27,3935.67 5160.27,3982.73 5063.3,4079.7 5063.3,4212.3 v1(5083,4232) v1@5084,4232
SPI_CS_MUX_CTRL: R104.1 S2.2 U11.6 | length 500.3
  Top Layer w5.5: U11.6@4918.45,3949.5 4938.62,3949.5 4955.08,3965.95 R104.1@4956.37,3965.95 4956.37,3968.15 4968.29,3980.07 5156.77,3980.07 5253.12,3883.71 5253.12,3805.71 5249.37,3801.96 S2.2@5249.37,3773.46
SPI_MISO1: R87.1 R166.2 RA3.4 U13.1 | length 2579.9
  Top Layer w5.5: v1(4796.56,3838.48) RA3.4@4796.56,3863.01 ; v1(5598.37,4202.46) R87.1@5619.36,4202.46 ; v1@6157,4355 v1(6157,4354) 6164.62,4346.38 U13.1@6187.6,4346.38
  Sig1 w4.2: v1(4796.56,3838.48) 4931.73,3973.65 5146.65,3973.65 5210.61,4037.61 5302.6,4037.61 5325.05,4015.16 5391.3,4015.16 5391.53,4015.4 5428.31,4015.4 5428.92,4014.79 5501.22,4014.79 5543,4056.58 5543,4093 5565.29,4115.29 5590.29,4115.29 5623,4148 ; v1(5598.37,4202.46) 5623,4177.83 5623,4148 ; v1(6157,4354) 6157,4325 6192,4290 6192,4276.28 6245.5,4222.78 6245.5,4206.5 6265.2,4186.8 6265.2,4055.2 6224,4014 5972.71,4014 5951,4035.71 5730.76,4035.71 5629,4137.48 5629,4142 5623,4148
  Bottom Layer w5.5: v1(5598.37,4202.46) 5580.62,4184.71 5580.62,4151.11 5592.98,4138.75 5629.24,4138.75 5700.37,4067.62 5700.37,3994.93 5719.62,3975.68 5719.62,3942.11 5728.8,3932.93 R166.2@5728.8,3913.6
SPI_MISO1_T: J6.2 R184.1 U14.3 | length 300.7
  Top Layer w5.5: R184.1@5562.38,3872.76 5564.27,3870.87 5564.27,3842.06 5564.27,3816.4 5614.75,3765.92 5673.29,3765.92 5699.72,3739.48 v1(5706.06,3739.48)
  Bottom Layer w5.5: v1(5706.06,3739.48) 5729.23,3762.65 U14.3@5729.23,3799.77
SPI_MOSI1: R86.1 RA3.3 U13.4 | length 2405.9
  Top Layer w5.5: v1(4759.94,3802.97) 4778.81,3821.84 4778.81,3861.01 RA3.3@4780.81,3863.01 ; v1(5561.37,4200.36) 5581.16,4180.57 R86.1@5619.21,4180.57 ; v1(6163,4288) 6163,4294.5 6167.63,4299.13 U13.4@6185.63,4299.13
  Sig1 w4.2: v1(4759.94,3802.97) 4777,3820.03 4777,3851.72 4907.53,3982.25 5141.25,3982.25 5206.84,4047.84 5407.74,4047.84 5432.4,4023.19 5497.74,4023.19 5534.35,4059.8 5534.35,4096.23 5562.3,4124.18 5585.72,4124.18 5613.67,4152.13 5613.67,4169.16 5602.37,4180.46 5570.47,4180.46 5561.37,4189.56 v1(5561.37,4200.36) 5578.77,4217.76 5622.24,4217.76 5644.97,4195.03 5644.97,4133.39 5733.44,4044.92 5970.08,4044.92 5982,4033 6228,4033 6253.7,4058.7 6253.7,4186.42 6237.1,4203.02 6237.1,4219.3 6168.4,4288 v1(6163,4288)
SRDY: R112.1 TP27.1 U8.31 | length 1258.8
  Top Layer w5.5: TP27.1@5172.19,4475.26 5198.65,4475.26 5219.44,4454.47 5219.44,4347.23 v1(5223.37,4343.3) ; U8.31@5841.41,3977.25 5841.41,3963.19 v1(5854.37,3950.23)
  Sig2 w4.2: v1(5223.37,4343.3) 5244.07,4364 5362.52,4364 5390.02,4336.5 5390.02,4303.18 5364.53,4277.68 5364.53,4241.83 ; 5364.51,4222.18 5364.51,4241.82 ; 5364.53,4222.17 5364.53,4204.99 5478.2,4091.31 5478.2,4057.2 5504.1,4031.3 5579.29,4031.3 5632.5,3978.1 5632.5,3921.84 5658.07,3896.26 5715.37,3896.26 5738.33,3919.22 5808.79,3919.22 5839.07,3949.51 5853.64,3949.51 v1(5854.37,3950.23)
  Bottom Layer w5.5: v1(5223.37,4343.3) 5247.55,4367.46 R112.1@5249.35,4367.46
SW0: L2.2 R53.2 U1.10 | length 179.3
  Top Layer w10: U1.10@3436.29,4219.15 3436.29,4258.18 3448.11,4269.99
  Top Layer w12: 3448.11,4269.99 3448.11,4304.96 L2.2@3474.98,4331.83
  Top Layer w15: L2.2@3481.55,4331.26 R53.2@3532.13,4331.26
SW0_CAP: C31.1 R53.1 | length 30
  Top Layer w8: R53.1@3532.13,4301.21 C31.1@3562.13,4301.21
SW1: L3.2 R54.2 U1.12 | length 204.1
  Top Layer w10: U1.12@3396.92,4219.15 3396.92,4258.18
  Top Layer w12: L3.2@3346.24,4331.83 3352.11,4331.83 3352.96,4330.97 3386.61,4297.33 3386.61,4267.21 3393.05,4260.77 3394.33,4260.77 3396.92,4258.18 ; L3.2@3358.24,4331.83 L3.2@3362.21,4331.83
  Top Layer w15: R54.2@3295.13,4330.97 3352.96,4330.97 L3.2@3357.38,4330.97
SW1_CAP: C32.1 R54.1 | length 27
  Top Layer w10: C32.1@3268.13,4301.17 R54.1@3295.13,4301.17
SW2: L4.2 R55.2 U1.25 | length 183
  Top Layer w10: U1.25@3436.29,4097.89 3436.29,4058.86 3448.11,4047.05
  Top Layer w12: 3448.11,4047.05 3448.11,4012.08 L4.2@3474.98,3985.21
  Top Layer w15: L4.2@3474.98,3985.21 3475.12,3985.35 R55.2@3529.23,3985.35
SW2_CAP: C33.1 R55.1 | length 29.7
  Top Layer w10: R55.1@3559.04,3985.35 C33.1@3559.04,4015.09
SW3: L5.2 R56.2 U1.23 | length 190.9
  Top Layer w10: 3385.11,4047.05 3396.92,4058.86 U1.23@3396.92,4097.89
  Top Layer w12: L5.2@3358.24,3985.21 3385.11,4012.08 3385.11,4047.05
  Top Layer w15: R56.2@3296.04,3985.21 3344.24,3985.21 L5.2@3358.24,3985.21
SW3_CAP: C34.1 R56.1 | length 32.9
  Top Layer w10: R56.1@3264.23,3985.21 3264.23,3999.74 C34.1@3277.23,4012.74
UART_MUX_CTRL1: R19.1 S1.1 U18.1 U18.5 | length 2495.2
  Top Layer w5.5: R19.1@3605.65,4263.69 3605.65,4281.55 3597.58,4289.62 3597.58,4325.01 3602.16,4329.59 3598,4333.74 3598,4333.92 ; U18.5@3621.94,4329.59 3602.34,4329.59 3598,4333.92 ; U18.1@3685.32,4354.59 3685.32,4401.45 3672.02,4414.75 3609.84,4414.75 3596.8,4401.71 3596.8,4380.94 3598,4379.73 3598,4333.92 ; v1(4891,4544) 4935.36,4544 4940,4539.36 4940,4539.1 4951.75,4527.35 4951.75,4516.44 4960.88,4507.3 5189.08,4507.3 5232.06,4464.32 5232.06,4407.44 5252.67,4386.84 5296.21,4386.84 5307.32,4397.95 5331.06,4397.95 5356.75,4372.25 5356.75,4215.32 5405.37,4166.69 S1.1@5405.37,4135.46
  Sig1 w4.2: v1(3685.37,4401.5) 3708.59,4378.28 4368.52,4378.28 4416.5,4426.26 4525.73,4426.26 4541.64,4442.17 4541.64,4492.34 4605.05,4555.75 4794.02,4555.75 4808.2,4569.94 4865.06,4569.94 v1(4891,4544)
UART_MUX_CTRL2: R1.1 S1.2 U15.1 U15.5 | length 378.6
  Top Layer w5.5: v1(5455.37,4090.46) S1.2@5455.37,4135.46
  Bottom Layer w5.5: U15.1@5479.68,4044.92 5479.68,4066.16 v1(5455.37,4090.46) 5467.81,4102.9 5504.1,4102.9 5515.37,4114.17 5579.7,4114.17 5594.81,4099.06 5594.81,4034.01 5583.16,4022.36 5579.67,4022.36 5577.06,4019.75 R1.1@5577.06,4018.46 5576.94,4018.34 U15.5@5544.64,4018.34
USB_5V: FL2.1 J1.1
USB_5V_B: FL14.1 J5.1
USB_AR_RS232RX: R61.1 U18.4 | length 202.6
  Top Layer w5.5: v1(3614.55,4394.36) 3626.27,4382.64 U18.4@3626.27,4356.16
  Sig1 w4.2: v1(3567.24,4279) 3595.25,4307.02 3595.25,4375.06 v1(3614.55,4394.36)
  Bottom Layer w5.5: v1(3567.24,4279) 3577.24,4269 R61.1@3577.24,4258.57
USB_AR_RS232TX: R63.2 U18.2 | length 520.9
  Top Layer w5.5: v1(3639.5,4397) 3665.64,4370.87 U18.2@3665.64,4356.16 U18.2@3665.64,4354.59
  Bottom Layer w5.5: R63.2@3604,4141.99 3604,4127.75 3575.57,4099.32 3530.68,4099.32 3499.86,4130.14 3499.86,4175.4 3515,4190.54 3515,4257.03 3531.62,4273.65 3531.62,4286.28 3639.5,4394.16 v1(3639.5,4397)
USB_DM: J1.2 R60.2 | length 918.6
  Sig2 w4: v1(3128.29,4140.98) 3135.69,4148.38 3192.56,4148.38 3243,4198.82 3351.87,4198.82 3515.49,4362.44 3719.76,4362.44 3767.48,4410.16 3804.08,4410.16 v1@3823.87,4429.94
  Bottom Layer w4: v1(3128.29,4140.98) 3135.04,4147.73 3144.74,4147.73 3153.29,4139.19 J1.2@3172.66,4139.19 ; v1@3824.12,4430.19 3823.95,4430.03 3823.95,4424.78 3841.44,4407.29 3841.44,4392.31 3846.33,4387.42 R60.2@3846.82,4387.42
  other v1: 3824.12,4429.69
USB_DP: J1.3 R41.2 | length 936.8
  Sig2 w4: v1(3128.29,4162.98) 3132.9,4158.38 3188.41,4158.38 3238.86,4208.82 3347.73,4208.82 3511.35,4372.44 3715.62,4372.44 3774.82,4431.64 3781.65,4431.64 3784.02,4429.27 3784.02,4422.57 3786.44,4420.16 3792.08,4420.16 v1@3801.87,4429.94
  Bottom Layer w4: v1(3128.29,4162.98) 3135.04,4156.23 3145.03,4156.23 3153.58,4164.78 J1.3@3172.66,4164.78 ; v1@3801.87,4429.94 3792.96,4421.03 3792.96,4416.74 3796.23,4413.48 3823.23,4413.48 3832.94,4403.77 3832.94,4395.05 R41.2@3825.31,4387.42 R41.2@3825.31,4390.31
  other v1: 3802.12,4429.69
VBUS: R64.2 R65.2 U3.8 | length 77.6
  Bottom Layer w10: R64.2@3715.38,4114.81 3715.38,4128.71 3718.57,4131.9 R65.2@3718.57,4143.04 3722.17,4146.64 U3.8@3722.17,4189.59
VCC_BA_3V3: C5.1 C6.2 C9.2 C10.2 C11.1 C12.2 C40.1 C72.2 C105.2 C107.1 C109.2 C117.1 C119.1 C123.1 C125.1 FL22.2 J3.1 J7.1 L8.1 R1.2 R13.1 R16.1 R18.1 R38.2 R72.1 R77.1 R78.1 R80.1 R81.1 R82.1 R89.2 R94.2 R95.2 R104.2 R111.2 R118.2 R124.2 R177.1 R178.1 TP13.1 U4.1 U4.3 U5.5 U6.4 U7.3 U7.28 U10.14 U10.15 U11.5 U12.5 U13.14 U14.11 U15.8 U16.5 U17.5 | length 2370.7
  Top Layer w5.5: v1(4943,3901) 4960.36,3918.36 C40.1@4960.36,3934.38 4961.45,3935.47 4961.45,3947.8 4967.08,3953.43 4974.15,3953.43 4977.37,3956.65 R104.2@4977.37,3965.92 ; v1(6206.79,4423.21) C107.1@6223.22,4423.21 6225,4421.43 U13.14@6225,4370
  Top Layer w6: U11.5@4920.42,3935.72 C40.1@4957.61,3935.72
  Top Layer w8: U16.5@4863.37,4175.21 4863.37,4196.33 4853.37,4206.33 C72.2@4853.37,4207.46 4848.26,4207.46 4832.37,4223.35 4832.37,4262.14 4841.23,4271 4903.58,4271 v1(4911.71,4279.13) ; R124.2@4875.2,4471.7 4893.34,4471.7 v1(4893.63,4472) ; R89.2@5837.41,4411.08 5837.41,4400.27 v1(5851.11,4386.56)
  Top Layer w10: R13.1@4647.44,4516.76 4657.26,4526.58 4657.11,4526.73 v1(4657.11,4540) ; v1(4846.16,3801.37) FL22.2@4846.16,3821.15 ; R177.1@4849.59,4089.43 4901.92,4089.43 4928.74,4116.25 4928.74,4143.73 v1(4932.61,4147.6) 4929.21,4151 R178.1@4929.21,4169.46 ; R111.2@5148.42,4116.46 5148.42,4085.16 v1(5152,4081.58) ; R118.2@6185,4432.52 6197.48,4432.52 v1(6206.79,4423.21) ; U17.5@6343.09,3827.61 6361.36,3827.61 6367.97,3821 6367.97,3790.43 6375.61,3782.79 C109.2@6375.61,3768.9 6386,3768.9 6392,3762.9 v1(6392,3749)
  Top Layer w12: R16.1@5577.42,4484.46 5577.42,4510.51 5593.1,4526.19 J7.1@5636.47,4526.19
  Top Layer w15: TP13.1@4798.18,3771.83 4798.18,3774.39 v1(4825.33,3801.54) ; v1(5997.89,3891.9) 5997.96,3891.83 L8.1@6040.76,3891.83
  Bottom Layer w5.5: R72.1@5443.4,3894.46 5443.9,3894.96 5463.87,3894.96 v1@5464.37,3895.46 ; C123.1@5499.4,3956.46 U15.8@5499.36,3991.77 ; C123.1@5499.4,3956.46 5515.37,3956.46 v1(5518.07,3959.16) ; v1(5569.37,4067.2) 5577.06,4059.51 R1.2@5577.06,4039.49
  Bottom Layer w6: U14.11@5760.73,3850.95 U14.11@5760.73,3866.08
  Bottom Layer w8: R38.2@5293.71,4235.46 5300.05,4229.12 v1(5321.26,4229.12) ; R18.1@5363.78,4049.5 5380.65,4066.37 v1(5380.65,4081.19) ; v1(5386.38,4363) 5391.75,4357.63 U12.5@5444.19,4357.63
  Bottom Layer w10: R80.1@5123,3909.96 5138.72,3894.24 v1(5138.72,3891.42) 5157.67,3891.42 5163.64,3897.38 U7.3@5203.84,3897.38 ; v1@5160.25,3821.31 5160.25,3802.52 5197.04,3802.52 5197.1,3802.58 5197.1,3803.37 5225.9,3832.17 U7.28@5225.9,3837.42 ; R77.1@5163.43,4041.09 5152,4052.52 v1(5152,4081.58) 5174.99,4081.58 5191.96,4064.61 5214.26,4064.61 5232.04,4082.38 ; R78.1@5164.52,3987.37 v1(5184.66,3987.37) ; v1(5187.37,4444.34) 5199.84,4444.34 5199.89,4444.39 R95.2@5211.14,4444.39 ; U5.5@5251.98,4123.67 U5.5@5251.98,4136.6 ; U5.5@5251.98,4134.63 5251.98,4117.32 ; C125.1@5259.81,4102.9 5246,4102.9 ; C125.1@5260.82,4102.9 5260.82,4108.48 5251.98,4117.32 ; R82.1@5272.85,4051.22 5272.85,4067.98 5265.47,4075.36 5239.06,4075.36 5232.04,4082.38 ; U10.14@5298.93,4495.99 U10.14@5298.93,4496.97 5298.93,4535.37 5297.21,4537.08 5297.21,4545.14 v1(5311.86,4559.79) 5323.37,4548.28 5323.37,4524.02 5314.67,4515.32 U10.15@5314.67,4496.97 U10.15@5314.67,4496.49 ; R81.1@5355.94,4081.19 v1(5380.65,4081.19) ; v1(5572.77,3748.43) 5584.13,3737.07 C12.2@5598.06,3737.07 5597.44,3737.69 U6.4@5597.44,3788.66 ; U14.11@5760.73,3866.08 5769.11,3874.46 5779.46,3874.46 5797.1,3892.1 C119.1@5797.1,3897.4 ; C119.1@5797.1,3899.2 C119.1@5797.1,3897.4 ; v1(5818.29,3892.41) 5816.12,3892.41 5811.31,3897.23 5797.27,3897.23 C119.1@5797.1,3897.4 ; v1(6381,3999) 6380.87,3998.87 C5.1@6380.87,3977 6380.87,3964.9 6407.77,3938 ; 5232.04,4082.38 5232.04,4103.02 5232.15,4102.9 5246,4102.9 ; 5246,4102.9 5251.98,4108.87 5251.98,4117.32
  Bottom Layer w15: U4.1@6332.97,3905.76 6336.62,3902.11 6336.62,3871.38 6351,3857 6398,3857 6409,3868 6409,3904.53 U4.3@6407.77,3905.76 6407.77,3938
  other v1: 4835,3786 5160.28,3821.34 5464.37,3894.6
VCLK_1V8: C65.1 C66.1 C67.1 C68.1 FL7.2 FL9.2 U2.C15 U2.C18 | length 210.6
  Top Layer w10: v1(3836.01,4299.09) U2.C15@3851.76,4314.84 ; U2.C18@3851.76,4409.33 v1(3867.5,4393.58)
  Sig2 w10: v1(3836.01,4299.09) 3849.3,4312.39 3849.3,4375.38 v1(3867.5,4393.58)
  Bottom Layer w10: v1(3867.5,4393.58) 3873.35,4399.42 C68.1@3873.35,4409.24 ; C65.1@3891,4188 3891,4192.68 3881.34,4202.34 C66.1@3897,4218
VCO_1V8: C62.1 C63.1 C64.1 FL7.1 U2.A12 U2.C11 | length 244.4
  Top Layer w10: C63.1@3737.19,4215.47 3759.7,4215.47 v1(3764,4211.16) 3779.58,4211.16 U2.A12@3788.76,4220.35 ; U2.C11@3851.76,4188.85 v1(3867.5,4173.11)
  Sig1 w10: v1(3764,4211.16) 3764,4163.79 3776.3,4151.49 3814.59,4151.49 3836.2,4173.11 v1(3867.5,4173.11)
VDDR: C29.1 C35.1 C36.1 L7.2 U8.45 U8.48 | length 293.7
  Top Layer w10: U8.45@5965.43,4160.32 5965.5,4160.39 5994.3,4160.39 v1(5994.37,4160.46) ; U8.48@5965.43,4219.38 C36.1@5996.43,4219.38 5996.43,4235.42 v1(6000.37,4239.36)
  Sig2 w20: v1(5994.37,4160.46) 5994.37,4233.36 v1(6000.37,4239.36)
  Bottom Layer w10: C35.1@5969.55,4181.25 5969.73,4181.08 5986.19,4181.08 5992.84,4174.43 v1@5992.84,4161.99 ; L7.2@5980.15,4080.83 5973.28,4087.71 C29.1@5973.28,4142.46 v1@5992.81,4161.99
VDDS: C25.1 C26.1 C27.1 C28.1 C86.1 L8.2 R110.2 U8.13 U8.22 U8.34 U8.44 | length 926.3
  Top Layer w10: R110.2@5320.41,3724.46 5392.48,3724.46 v1(5432.29,3764.27) ; v1@5644.38,4244.36 5639.38,4239.36 C25.1@5639.38,4224.38 5641.18,4224.38 5646.18,4219.38 U8.13@5697.71,4219.38 ; v1@5645.38,4062.2 5640.38,4057.2 C26.1@5640.38,4042.21 U8.22@5697.71,4042.21 ; v1(5900.47,3950.73) U8.34@5900.47,3977.25 ; U8.44@5965.43,4140.64 5965.6,4140.46 5998.84,4140.46 6002.56,4136.74 6027.29,4136.74 6035.56,4128.46 C27.1@6037.36,4128.46 6037.37,4113.46 v1(6032.37,4108.46) ; L8.2@6028.3,3947.02 L8.2@6028.37,3946.95
  Top Layer w12: v1(5963.12,3949.86) 5966.73,3946.25 C28.1@5984.12,3946.25 5984.82,3946.95 L8.2@6028.37,3946.95
  Sig1 w10: v1(5432.29,3764.27) 5469.1,3801.08 5469.1,3832.9 5486.52,3850.32 5486.52,3972.24 5523.95,4009.66 5592.41,4009.66 5593.07,4009 v1(5646.27,4062.2)
  Bottom Layer w10: C86.1@5900.43,3935.35 v1@5900.43,3950.7
  other v1: 5645.27,4244.36
VIOIN_1V8: C59.1 C60.1 C61.1 FL10.2 U2.B1 U2.F1 U2.K1 U2.U2 U2.V11 | length 585.6
  Top Layer w5.5: v1(3804.51,3858.15) U2.B1@3820.26,3873.89 ; v1(3930.5,3858.15) U2.F1@3946.24,3873.89 ; U2.K1@4072.23,3873.89 v1(4087.98,3858.15) ; U2.U2@4292.7,3905.39 4309.57,3888.52 4340.79,3888.52 4346.63,3882.68 C60.1@4378.33,3882.68 ; v1(4308.45,4173.11) U2.V11@4324.2,4188.85
  Top Layer w10: v1(4276.95,3921.14) U2.U2@4292.7,3905.39
  PWR1 w10: v1(4087.98,3992.71) 4152.55,3992.71 4213.7,4053.85 4213.7,4143.54 4243.27,4173.11 v1(4308.45,4173.11)
  Bottom Layer w5.5: C61.1@4282,4185.3 4292.87,4185.3 4305.07,4173.11 v1(4308.45,4173.11)
  other v1: 4024.98,3992.71 4056.48,3992.71
X32K_Q1: C19.1 U8.3 Y3.1 | length 225
  Top Layer w5.5: C19.1@5765.79,4380.71 5786.59,4380.71 5797.72,4369.58 Y3.1@5808.9,4369.58 5826.24,4369.58 5836.84,4358.98 5836.84,4339.08 5842.05,4333.87 5842.05,4309.95 5886.47,4265.53 5894.37,4265.53 5900.47,4259.44 U8.3@5900.47,4244.97
X32K_Q2: C20.1 U8.4 Y3.2 | length 164.4
  Top Layer w5.5: C20.1@5765.79,4315.14 5769.64,4315.14 5780.77,4326.27 Y3.2@5808.9,4326.27 5818.54,4326.27 5825.63,4319.18 5825.63,4308.18 5874.57,4259.24 5874.57,4258.26 5880.78,4252.05 U8.4@5880.78,4244.97
X48M_N: C18.1 U8.46 Y2.3 | length 187.6
  Top Layer w4: U8.46@5965.43,4180.01 5972.51,4180.01 5976.86,4184.35 6008.44,4184.35 6031.22,4184.35 C18.1@6038.8,4176.76 6038.8,4178.56 6049.1,4188.85 6107.66,4188.85 6126.55,4169.96 Y2.3@6126.55,4162.29
X48M_P: C17.1 U8.47 Y2.1 | length 140
  Top Layer w4: U8.47@5965.43,4199.69 5972.51,4199.69 5976.86,4195.35 6013,4195.35 6031.22,4195.35 6033.83,4197.96 6035.63,4197.96 6038.8,4201.13 C17.1@6038.8,4202.93 6041.88,4199.85 6048.29,4199.85 6052.65,4199.85 6073.36,4199.85 Y2.1@6090.91,4217.41
XIN32: C38.1 U7.27 Y4.1 | length 112.9
  Bottom Layer w5.5: Y4.1@5241.17,3740.88 5241.17,3762.93 5251.43,3773.2 5251.43,3795.13 5253.12,3796.82 5253.12,3820.41 5245.67,3827.87 U7.27@5245.67,3845.7
XOUT32: C39.1 U7.26 Y4.2 | length 112.7
  Bottom Layer w5.5: U7.26@5265.35,3845.7 5265.35,3819.96 5275.14,3810.17 5275.14,3795.3 5275.14,3774.34 5284.47,3765.01 Y4.2@5284.47,3740.88
pads on no net: A1.2-3 A1.5-6 Designator1. Designator1_1. Designator2. Designator2_1. Designator3. Designator3_1. Designator4. Designator4_1. Designator5. Designator5_1. Designator5_2. Designator6. Designator7. Designator8. Designator10. Designator22_1. Designator23. FID1.1 FID2.1 FID3.1 FID4.1 FID5.1 FID6.1 J1.4 J2.1 J2.3 J2.4 J2.5 J2.6 J2.7 J2.9 J2.MH1 J2.MH2 J4.4 J5.2 J5.3 J5.4 J6.4 J9.2@5173.9,4283.6 J9.3@5292.01,4283.6 RA2.1 RA2.8 RA5.4 RA5.5 S2.4 S2.5 U1. U2.A3 U2.A4 U2.B3 U2.B4 U2.B5 U2.C3 U2.C4 U2.C5 U3.10 U3.11 U3.14 U3.15 U3.16 U3.18 U3.19 U3.21 U3.22 U3.23 U3.24 U7.1 U7.7 U7.8 U7.12 U7.13 U7.15 U7.16 U7.18 U7.21 U7.22 U7.23 U7.24 U8.5 U8.6 U8.9 U8.10 U8.12 U8.18 U8.19 U8.20 U8.28 U8.32 U8.36 U8.37 U8.38 U8.39 U8.40 U8.41 U8.42 U8.43 U12.9@5457.58,4302.51 U12.9@5507.58,4302.51 U17.9@6287.97,3841 U17.9@6287.97,3891 U19.9@6109.37,3825.66 U19.9@6109.37,3875.27

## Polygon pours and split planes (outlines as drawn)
RE on Top Layer "Top Layer-RE" (solid, remove dead copper, pour order 493): 6540.72,4398.89 6564.34,4398.89 6564.34,4587.86 6540.72,4587.86
5V_IN_B on Top Layer "Top Layer-5V_IN_B" (solid, remove dead copper, pour order 491): 6197,4124 6206,4133 6276,4133 6318,4133 6325,4126 6325,4051 6321,4047 6205,4047 6197,4055
USB_5V_B on Top Layer "Top Layer-USB_5V_B" (solid, remove dead copper, pour order 489): 6338,4138.4 6378.89,4138.4 6395.42,4121.87 6402.92,4114.37 6470,4114.37 6476,4108.37 6476,4096.37 6471,4091.37 6338,4091.37 6338,4113.37
no net on Top Layer "Top Layer-No Net" (solid, remove dead copper, pour order 477): 6335,4190
GND on Top Layer " " (solid, remove dead copper, pour order 428): 6462.4,4602.09 6462.4,4476 6094.58,4476 6094.58,4239.36 5840,4239.36 5840,4602.01
GND on Top Layer " " (solid, remove dead copper, pour order 495): 6117.79,4247.89 6117.79,4457 6461.9,4457 6461.9,4318.4 6592,4318.4 6592,3727 6558.63,3693.63 6491,3693.63 4391.1,3693.98 4391.1,4599.81 5818.71,4599.81 5818.71,4287.56 5894.15,4212.11 6082.01,4212.11
GND on Top Layer " " (solid, remove dead copper, pour order 465): 3261.1,4211.1 3261.1,4188.61 3268.49,4181.22 3268.49,4153.29 3150.01,4153.29 3125.63,4177.67 3125.63,4270.32 3146.11,4290.8 3191.47,4290.8 3203.02,4279.24 3203.02,4230.58 3222.51,4211.1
